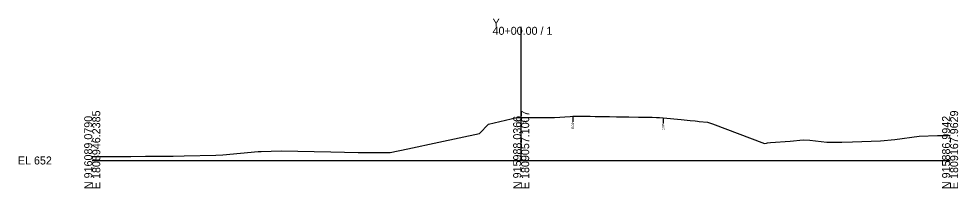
# Model space of a CAD drawing. Extents: x -26 to 3303, y -30 to 9580.
# Drawn here: x 2974.3 to 3302.8, y -9.7 to 49.5 of the extents above; entities that cross this region are included whole.
import ezdxf

# ---------------------------------------------------------------- set-up
doc = ezdxf.new("R2010")
doc.units = 0
for name, color, linetype in [('Exist Cross Section Cell', 7, 'Continuous'), ('Exist XS Center Line Elevation Label', 7, 'Continuous'), ('Exist XS Ground Line', 7, 'Continuous'), ('Old_Level_10', 7, 'Continuous')]:
    doc.layers.add(name, color=color, linetype=linetype)

msp = doc.modelspace()

# ---------------------------------------------------------------- linework, layer by layer
at = {"layer": 'Exist Cross Section Cell'}
for p, q in [((3150, 0), (3150, 46.73)), ((3000, 0), (3150, 0)), ((3150, 0), (3300, 0))]:
    msp.add_line(p, q, dxfattribs=at)
at = {"layer": 'Exist XS Ground Line'}
msp.add_lwpolyline([(3000, 1.4), (3005.09, 1.39), (3013.48, 1.4), (3018.62, 1.56), (3028.32, 1.5), (3032.15, 1.6), (3043.17, 1.91), (3045.68, 1.93), (3058.01, 3.12), (3058.64, 3.18), (3059.04, 3.18), (3066.01, 3.38), (3083.43, 2.98), (3093.01, 2.76), (3104.24, 2.84), (3110.39, 4.06), (3121.19, 6.42), (3135.43, 9.42), (3138.62, 12.73), (3148.49, 15.06), (3150.03, 15.01), (3150.44, 15.04), (3161.66, 14.98), (3167.08, 15.42), (3168.1, 15.53), (3169.71, 15.52), (3170.76, 15.51), (3171.79, 15.5), (3172.53, 15.48), (3172.95, 15.47), (3174.17, 15.44), (3175.89, 15.42), (3177.51, 15.41), (3178.53, 15.39), (3179.61, 15.37), (3180.31, 15.36), (3180.93, 15.35), (3183.36, 15.3), (3184.23, 15.28), (3185.74, 15.25), (3187.05, 15.22), (3187.7, 15.22), (3191.05, 15.17), (3194.47, 15.11), (3195.8, 15.09), (3197.3, 15.03), (3198.02, 15.01), (3198.42, 14.99), (3199.62, 14.96), (3205.92, 14.31), (3209.11, 13.98), (3210.86, 13.8), (3211.71, 13.72), (3212.28, 13.66), (3215.19, 13.39), (3216.89, 12.84), (3235.14, 5.94), (3235.83, 6.09), (3236.15, 6.15), (3237.22, 6.31), (3244.09, 6.74), (3248.63, 7.2), (3251, 7.05), (3256.84, 6.44), (3262.17, 6.44), (3265.85, 6.52), (3275.7, 6.91), (3280.69, 7.3), (3289.23, 8.47), (3295.54, 8.76), (3299.31, 8.73), (3300, 8.84)], dxfattribs=at)
at = {"layer": 'Old_Level_10'}
for p, q in [((3168.1, 15.53), (3168.1, 13.48)), ((3199.62, 14.96), (3199.62, 12.91))]:
    msp.add_line(p, q, dxfattribs=at)

# ---------------------------------------------------------------- texts
at = {"layer": 'Exist Cross Section Cell'}
for s, p in [('Y', (3140, 46.73)), ('40+00.00 / 1', (3140, 43.93)), ('EL 652', (2974, -1.4))]:
    msp.add_text(s, height=2.8, dxfattribs=at).set_placement(p)
for s, p in [('E 1808946.2385', (3002.8, -10)), ('E 1809057.1007', (3152.8, -10)), ('E 1809167.9629', (3302.8, -10)), ('N 916089.0790', (3000, -10)), ('N 915988.0366', (3150, -10)), ('N 915886.9942', (3300, -10))]:
    msp.add_text(s, height=2.8, rotation=90, dxfattribs=at).set_placement(p)
at = {"layer": 'Exist XS Center Line Elevation Label'}
msp.add_text('667.01', height=1, dxfattribs=at).set_placement((3148.04, 13.01))
at = {"layer": 'Old_Level_10'}
for p in [(3168.49, 11.08), (3200.01, 10.51)]:
    msp.add_text('EOP', height=0.787, rotation=90, dxfattribs=at).set_placement(p)

doc.saveas('drawing.dxf')
